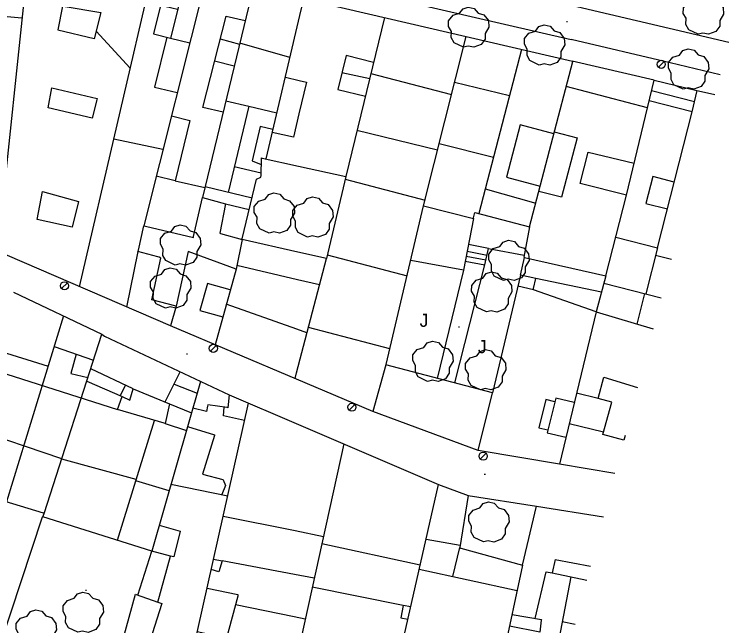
# Model space of a CAD drawing. Extents: x 431390 to 432653, y 4586754 to 4589600.
# Drawn here: x 432092.3 to 432163.1, y 4587535.4 to 4587596 of the extents above; entities that cross this region are included whole.
import ezdxf

# ---------------------------------------------------------------- set-up
doc = ezdxf.new("R2010")
doc.units = 0
for name, color, linetype in [('COM_03LS_LN', 7, 'Continuous'), ('COM_17LS_LN', 7, 'Continuous'), ('CON_01_LN', 7, 'Continuous'), ('CON_01FI_LN', 7, 'Continuous'), ('CON_03_LN', 7, 'Continuous'), ('CON_04_LN', 7, 'Continuous'), ('CON_16_LN', 7, 'Continuous'), ('CON_23_LN', 7, 'Continuous'), ('CON_29_LN', 7, 'Continuous'), ('ENE_06_PT', 7, 'Continuous'), ('ORO_03_PT', 7, 'Continuous'), ('TOP_15JA_TX', 7, 'Continuous'), ('VEG_03_PT', 7, 'Continuous'), ('VEG_04_LN', 7, 'Continuous'), ('VEG_06_LN', 7, 'Continuous')]:
    doc.layers.add(name, color=color, linetype=linetype)

msp = doc.modelspace()

# ---------------------------------------------------------------- linework, layer by layer
at = {"layer": 'COM_03LS_LN'}
for points in [[(432148.069, 4587596.828), (432163.121, 4587593.267)], [(432162.272, 4587590.047), (432157.309, 4587591.225), (432147.484, 4587593.556)]]:
    msp.add_lwpolyline(points, dxfattribs=at)
at = {"layer": 'COM_17LS_LN'}
msp.add_lwpolyline([(432070.895, 4587611.638), (432120.634, 4587599.769), (432147.484, 4587593.556)], dxfattribs=at)
at = {"layer": 'CON_01_LN'}
for points in [[(432106.208, 4587601.193), (432120.615, 4587597.708), (432120.995, 4587597.616), (432147.631, 4587591.384)], [(432155.734, 4587589.503), (432147.612, 4587591.388)], [(432155.734, 4587589.503), (432159.823, 4587588.532), (432161.753, 4587588.075)], [(432151.84, 4587550.473), (432146.326, 4587551.413), (432138.281, 4587552.763), (432127.829, 4587556.647), (432120.26, 4587559.847), (432107.753, 4587565.134), (432088.191, 4587573.557), (432088.214, 4587573.584)], [(432092.203, 4587568.485), (432100.973, 4587564.312), (432101.229, 4587564.125), (432113.576, 4587558.283), (432120.218, 4587555.446), (432134.346, 4587549.412), (432137.277, 4587548.31)], [(432144.072, 4587547.245), (432150.707, 4587546.175)]]:
    msp.add_lwpolyline(points, dxfattribs=at)
at = {"layer": 'CON_01FI_LN'}
for points in [[(432123.226, 4587571.811), (432120.378, 4587572.458), (432114.871, 4587573.708), (432114.883, 4587573.755), (432116.309, 4587579.681), (432116.733, 4587579.891), (432116.753, 4587580.055), (432116.784, 4587581.798), (432116.85, 4587581.779), (432120.458, 4587580.992), (432125.144, 4587579.971), (432123.226, 4587571.811)], [(432108.337, 4587567.104), (432105.927, 4587567.726), (432106.82, 4587571.868), (432106.643, 4587571.942), (432106.502, 4587571.98), (432104.519, 4587572.51), (432104.597, 4587572.648), (432105.12, 4587575.073), (432105.292, 4587575.039), (432110.047, 4587573.898), (432110.053, 4587573.998), (432110.937, 4587577.872), (432113.209, 4587577.237), (432112.659, 4587574.33), (432112.715, 4587574.294), (432114.871, 4587573.708), (432114.268, 4587570.766), (432109.511, 4587572.517), (432108.337, 4587567.104)], [(432139.69, 4587558.497), (432129.133, 4587561.255), (432129.151, 4587561.297), (432132.868, 4587577.053), (432137.815, 4587575.785), (432137.802, 4587575.858), (432137.941, 4587576.391), (432143.372, 4587574.965), (432142.798, 4587571.962), (432142.868, 4587571.912), (432150.929, 4587570.089), (432149.982, 4587566.519), (432143.77, 4587568.7), (432143.777, 4587568.856), (432144.01, 4587569.843), (432142.472, 4587570.176), (432139.69, 4587558.497)], [(432107.233, 4587555.449), (432107.131, 4587555.481), (432102.504, 4587556.851), (432102.972, 4587558.141), (432103.742, 4587557.759), (432104.075, 4587558.897), (432107.678, 4587557.41), (432107.233, 4587555.449)], [(432102.061, 4587530.339), (432104.307, 4587538.521), (432104.355, 4587538.486), (432106.5, 4587537.738), (432107.773, 4587542.281), (432105.905, 4587542.792), (432095.119, 4587546.184), (432095.24, 4587546.531), (432095.183, 4587546.547), (432086.343, 4587549.245), (432074.662, 4587552.564), (432075.907, 4587557.139), (432072.681, 4587558.016), (432071.631, 4587553.82), (432072.586, 4587552.504), (432072.558, 4587552.399), (432071.129, 4587547.627), (432071.982, 4587546.582), (432070.58, 4587542.529), (432071.484, 4587541.753), (432071.456, 4587541.694), (432070.713, 4587539.118)], [(432137.277, 4587548.31), (432136.457, 4587543.157), (432136.573, 4587543.097), (432142.682, 4587541.38), (432144.072, 4587547.245)]]:
    msp.add_lwpolyline(points, dxfattribs=at)
at = {"layer": 'CON_03_LN'}
for points in [[(432098.74, 4587569.015), (432106.208, 4587601.193)], [(432111.36, 4587599.947), (432105.12, 4587575.073)], [(432116, 4587598.824), (432110.937, 4587577.872)], [(432117.241, 4587581.694), (432120.598, 4587595.933), (432120.995, 4587597.616)], [(432129.002, 4587595.742), (432125.144, 4587579.971)], [(432132.868, 4587577.053), (432137.087, 4587593.851)], [(432142.586, 4587592.564), (432138.339, 4587576.286)], [(432143.372, 4587574.965), (432147.651, 4587591.379)], [(432150.929, 4587570.089), (432152.976, 4587578.109), (432155.734, 4587589.503)], [(432159.508, 4587586.369), (432160.003, 4587588.489)], [(432156.067, 4587572.881), (432159.508, 4587586.369)], [(432125.075, 4587579.677), (432133.006, 4587577.602)], [(432156.067, 4587572.881), (432154.899, 4587568.309)], [(432104.519, 4587572.51), (432103.417, 4587567.001)], [(432120.119, 4587559.907), (432120.265, 4587560.467), (432123.226, 4587571.811)], [(432114.268, 4587570.766), (432112.182, 4587563.262)], [(432150.739, 4587569.371), (432156.438, 4587567.916)], [(432108.337, 4587567.104), (432107.753, 4587565.134)], [(432149.982, 4587566.519), (432146.326, 4587551.413)], [(432097.152, 4587566.13), (432091.514, 4587547.667)], [(432095.24, 4587546.531), (432100.973, 4587564.312)], [(432129.133, 4587561.255), (432127.829, 4587556.647)], [(432110.746, 4587559.622), (432105.905, 4587542.792)], [(432138.281, 4587552.763), (432139.69, 4587558.497)], [(432108.976, 4587528.373), (432115.5, 4587557.461)], [(432124.954, 4587553.423), (432119.988, 4587530.872), (432118.821, 4587525.574)], [(432128.328, 4587522.871), (432134.346, 4587549.412)], [(432142.682, 4587541.38), (432138.762, 4587523.143), (432138.079, 4587520.171)], [(432145.915, 4587541.945), (432149.421, 4587541.297)]]:
    msp.add_lwpolyline(points, dxfattribs=at)
at = {"layer": 'CON_04_LN'}
for points in [[(432105.708, 4587599.038), (432093.684, 4587601.781), (432090.594, 4587572.522)], [(432110.633, 4587597.049), (432108.729, 4587597.527), (432107.771, 4587593.683), (432109.674, 4587593.226)], [(432100.198, 4587593.624), (432096.602, 4587594.458), (432096.629, 4587594.51), (432097.075, 4587596.869), (432097.129, 4587596.846), (432100.867, 4587596.215), (432100.198, 4587593.624)], [(432108.477, 4587596.514), (432106.781, 4587596.937), (432106.074, 4587594.106), (432107.771, 4587593.683)], [(432093.038, 4587595.667), (432089.762, 4587595.95)], [(432112.98, 4587586.325), (432110.98, 4587586.809), (432113.278, 4587595.849), (432115.183, 4587595.444)], [(432107.407, 4587593.774), (432106.169, 4587588.803), (432108.439, 4587588.304)], [(432127.91, 4587591.28), (432125.185, 4587591.947), (432124.364, 4587588.593), (432127.09, 4587587.925)], [(432114.084, 4587590.894), (432112.143, 4587591.386)], [(432119.156, 4587589.815), (432120.538, 4587589.489), (432121.252, 4587589.321), (432120.506, 4587586.157), (432119.961, 4587583.842), (432117.864, 4587584.336)], [(432155.072, 4587586.769), (432146.998, 4587588.874)], [(432100.482, 4587587.68), (432100.457, 4587587.567), (432099.986, 4587585.752), (432095.652, 4587586.753), (432096.014, 4587588.763), (432100.482, 4587587.68)], [(432159.741, 4587587.369), (432155.481, 4587588.456)], [(432113.258, 4587587.478), (432115.533, 4587586.929), (432113.479, 4587578.369)], [(432159.508, 4587586.369), (432155.239, 4587587.458)], [(432115.533, 4587586.929), (432118.32, 4587586.271)], [(432107.856, 4587585.98), (432109.67, 4587585.526), (432108.224, 4587579.522), (432111.175, 4587578.856)], [(432117.928, 4587584.609), (432116.659, 4587584.909), (432115.855, 4587581.508), (432116.773, 4587581.158)], [(432145.778, 4587584.196), (432142.449, 4587585.065), (432141.1, 4587579.898), (432144.424, 4587579)], [(432134.257, 4587582.584), (432126.254, 4587584.507)], [(432145.824, 4587584.371), (432148.082, 4587583.783), (432146.548, 4587577.894), (432144.289, 4587578.482)], [(432107.018, 4587582.639), (432102.137, 4587583.65)], [(432139.789, 4587581.845), (432134.411, 4587583.195)], [(432152.976, 4587578.109), (432148.404, 4587579.277), (432149.186, 4587582.373), (432153.745, 4587581.285)], [(432116.757, 4587580.289), (432114.093, 4587580.928)], [(432108.224, 4587579.522), (432106.354, 4587579.991)], [(432157.728, 4587579.391), (432155.581, 4587579.939), (432154.905, 4587577.293), (432157.052, 4587576.744)], [(432115.855, 4587577.795), (432111.191, 4587578.922)], [(432098.636, 4587577.481), (432098.001, 4587574.912), (432094.56, 4587575.678), (432095.075, 4587578.455), (432098.636, 4587577.481)], [(432138.974, 4587578.721), (432143.987, 4587577.324)], [(432113.209, 4587577.237), (432115.583, 4587576.665)], [(432151.912, 4587573.941), (432156.067, 4587572.881)], [(432123.316, 4587572.196), (432131.229, 4587570.107)], [(432155.877, 4587572.139), (432157.449, 4587571.748)], [(432122.544, 4587569.197), (432120.352, 4587569.715), (432114.344, 4587571.136)], [(432113.698, 4587568.715), (432111.426, 4587569.347), (432110.681, 4587566.668), (432112.953, 4587566.036)], [(432143.77, 4587568.7), (432142.209, 4587569.071)], [(432154.034, 4587565.312), (432154.805, 4587568.333)], [(432149.982, 4587566.519), (432155.627, 4587564.838)], [(432090.422, 4587562.748), (432095.628, 4587561.139)], [(432096.227, 4587563.102), (432100.144, 4587561.742)], [(432098.429, 4587562.337), (432097.888, 4587560.404), (432099.583, 4587560.002)], [(432089.836, 4587560.861), (432102.504, 4587556.851)], [(432104.075, 4587558.897), (432099.861, 4587560.864)], [(432107.248, 4587557.587), (432108.736, 4587560.573)], [(432152.839, 4587554.261), (432152.709, 4587553.792), (432150.654, 4587554.36), (432151.537, 4587557.555), (432150.172, 4587557.931), (432150.753, 4587560.041), (432154.091, 4587559.012)], [(432099.467, 4587559.64), (432102.972, 4587558.141)], [(432103.297, 4587559.26), (432102.761, 4587558.231)], [(432108.128, 4587559.352), (432110.409, 4587558.449)], [(432150.172, 4587557.931), (432148.029, 4587558.449)], [(432113.576, 4587558.283), (432113.437, 4587556.994), (432113.371, 4587557.042), (432111.477, 4587557.314), (432111.438, 4587557.17), (432111.351, 4587556.628), (432109.981, 4587556.961)], [(432145.877, 4587557.615), (432144.978, 4587557.833), (432144.299, 4587555.036), (432145.199, 4587554.817)], [(432147.806, 4587557.527), (432145.964, 4587557.973), (432145.132, 4587554.539), (432146.974, 4587554.092)], [(432107.678, 4587557.41), (432109.855, 4587556.523)], [(432115.115, 4587555.743), (432113.011, 4587556.214), (432113.082, 4587557.083)], [(432102.498, 4587543.863), (432106.181, 4587555.762)], [(432107.233, 4587555.449), (432109.345, 4587554.752)], [(432109.462, 4587555.157), (432112.13, 4587554.33), (432112.123, 4587554.275), (432110.933, 4587550.431), (432112.962, 4587549.897), (432113.004, 4587549.844), (432113.226, 4587549.312), (432112.851, 4587548.392)], [(432150.714, 4587554.576), (432147.292, 4587555.403)], [(432107.811, 4587549.417), (432113.439, 4587548.273)], [(432112.987, 4587546.256), (432120.119, 4587544.82), (432122.935, 4587544.253)], [(432106.64, 4587545.349), (432108.717, 4587544.766), (432108.083, 4587542.207), (432107.773, 4587542.281)], [(432122.78, 4587543.551), (432132.533, 4587541.415)], [(432136.488, 4587543.352), (432133.109, 4587543.956)], [(432135.761, 4587540.273), (432136.457, 4587543.157)], [(432112.033, 4587542.003), (432112.897, 4587541.81), (432112.558, 4587540.726), (432111.802, 4587540.975)], [(432145.915, 4587541.945), (432145.624, 4587540.641), (432149.051, 4587539.894)], [(432132.436, 4587540.99), (432142.148, 4587538.897)], [(432147.462, 4587540.24), (432145.688, 4587530.905), (432145.628, 4587530.945), (432144.357, 4587531.208), (432143.097, 4587525.608), (432143.222, 4587525.568), (432144.296, 4587525.404), (432143.773, 4587522.351), (432138.837, 4587523.493)], [(432111.388, 4587539.128), (432114.459, 4587538.468), (432114.428, 4587538.317), (432113.336, 4587534.147), (432113.286, 4587534.168), (432110.409, 4587534.764)], [(432106.5, 4587537.738), (432106.894, 4587537.605), (432105.486, 4587533.117), (432103.065, 4587533.996)], [(432114.212, 4587537.492), (432120.039, 4587536.294), (432121.132, 4587536.069)], [(432131.589, 4587537.254), (432130.839, 4587537.401), (432130.612, 4587536.175), (432131.315, 4587536.046)], [(432141.636, 4587536.513), (432144.544, 4587536), (432144.532, 4587535.931), (432144.384, 4587534.749), (432141.385, 4587535.346)], [(432147.896, 4587535.512), (432146.61, 4587535.757)]]:
    msp.add_lwpolyline(points, dxfattribs=at)
at = {"layer": 'CON_16_LN'}
for points in [[(432137.815, 4587575.785), (432136.822, 4587570.659), (432131.584, 4587571.61)], [(432142.472, 4587570.176), (432142.868, 4587571.912)], [(432150.498, 4587568.466), (432144.01, 4587569.843)], [(432137.277, 4587548.31), (432144.072, 4587547.245)], [(432104.513, 4587538.431), (432105.905, 4587542.792)]]:
    msp.add_lwpolyline(points, dxfattribs=at)
at = {"layer": 'CON_23_LN'}
for points in [[(432137.188, 4587572.547), (432139.164, 4587572.164)], [(432139.315, 4587572.809), (432137.313, 4587573.194)], [(432138.938, 4587571.194), (432139.315, 4587572.809)], [(432137.093, 4587572.058), (432139.051, 4587571.679)], [(432136.998, 4587571.569), (432138.938, 4587571.194)]]:
    msp.add_lwpolyline(points, dxfattribs=at)
at = {"layer": 'CON_29_LN'}
for points in [[(432103.776, 4587590.715), (432100.394, 4587594.382)], [(432112.708, 4587593.606), (432114.612, 4587593.082)], [(432119.614, 4587591.759), (432114.636, 4587593.179)], [(432124.772, 4587590.259), (432127.521, 4587589.688)], [(432127.642, 4587590.183), (432135.641, 4587588.092)], [(432135.945, 4587589.303), (432141.393, 4587587.991)], [(432121.303, 4587564.443), (432120.306, 4587564.796), (432113.299, 4587567.279)], [(432129.518, 4587562.853), (432121.445, 4587564.987)], [(432096.982, 4587551.935), (432088.006, 4587554.97)], [(432104.367, 4587549.9), (432096.978, 4587551.923)], [(432107.625, 4587548.772), (432104.324, 4587549.761)], [(432122.018, 4587540.089), (432120.078, 4587540.455), (432112.897, 4587541.81)], [(432143.928, 4587536.109), (432145.009, 4587540.731), (432145.624, 4587540.641)], [(432130.839, 4587537.401), (432121.823, 4587539.204)]]:
    msp.add_lwpolyline(points, dxfattribs=at)
at = {"layer": 'ENE_06_PT'}
for p, q in [((432156.716, 4587591.368), (432156.15, 4587590.802)), ((432097.539, 4587569.395), (432096.973, 4587568.829)), ((432112.3, 4587563.189), (432111.734, 4587562.623)), ((432126.039, 4587557.351), (432125.473, 4587556.785)), ((432139.057, 4587552.491), (432138.491, 4587551.925))]:
    msp.add_line(p, q, dxfattribs=at)
for centre in [(432156.433, 4587591.085), (432097.256, 4587569.112), (432112.017, 4587562.906), (432125.756, 4587557.068), (432138.774, 4587552.208)]:
    msp.add_circle(centre, 0.4, dxfattribs=at)
at = {"layer": 'ORO_03_PT'}
for p, q in [((432147.047, 4587595.35), (432147.147, 4587595.35)), ((432136.33, 4587565.046), (432136.43, 4587565.046)), ((432109.341, 4587562.376), (432109.441, 4587562.376)), ((432138.888, 4587550.419), (432138.988, 4587550.419)), ((432099.354, 4587538.903), (432099.454, 4587538.903))]:
    msp.add_line(p, q, dxfattribs=at)
at = {"layer": 'VEG_03_PT'}
for points in [[(432160.088, 4587594.079), (432159.161, 4587594.514), (432158.873, 4587595.035), (432158.896, 4587595.649), (432158.614, 4587596.141), (432158.622, 4587596.704), (432159.063, 4587597.239), (432159.716, 4587597.443), (432160.051, 4587597.894), (432160.577, 4587598.064), (432161.157, 4587597.931), (432161.557, 4587597.465), (432162.131, 4587597.295), (432162.565, 4587596.712), (432162.614, 4587596.07), (432162.231, 4587595.423), (432162.231, 4587594.873), (432161.859, 4587594.339), (432161.12, 4587594.064), (432160.555, 4587594.192), (432160.088, 4587594.079)], [(432136.812, 4587592.786), (432135.885, 4587593.221), (432135.597, 4587593.742), (432135.62, 4587594.356), (432135.338, 4587594.848), (432135.346, 4587595.411), (432135.787, 4587595.946), (432136.44, 4587596.15), (432136.775, 4587596.601), (432137.301, 4587596.771), (432137.881, 4587596.638), (432138.281, 4587596.172), (432138.855, 4587596.002), (432139.289, 4587595.419), (432139.338, 4587594.777), (432138.955, 4587594.13), (432138.955, 4587593.58), (432138.583, 4587593.046), (432137.844, 4587592.771), (432137.279, 4587592.899), (432136.812, 4587592.786)], [(432144.339, 4587591.015), (432143.412, 4587591.45), (432143.124, 4587591.971), (432143.147, 4587592.585), (432142.865, 4587593.077), (432142.873, 4587593.64), (432143.314, 4587594.175), (432143.967, 4587594.379), (432144.302, 4587594.83), (432144.828, 4587595), (432145.408, 4587594.867), (432145.808, 4587594.401), (432146.382, 4587594.231), (432146.816, 4587593.648), (432146.865, 4587593.006), (432146.482, 4587592.359), (432146.482, 4587591.809), (432146.11, 4587591.275), (432145.371, 4587591), (432144.806, 4587591.128), (432144.339, 4587591.015)], [(432158.618, 4587588.631), (432157.691, 4587589.066), (432157.403, 4587589.587), (432157.426, 4587590.201), (432157.144, 4587590.693), (432157.152, 4587591.256), (432157.593, 4587591.791), (432158.246, 4587591.995), (432158.581, 4587592.446), (432159.107, 4587592.616), (432159.687, 4587592.483), (432160.087, 4587592.017), (432160.661, 4587591.847), (432161.095, 4587591.264), (432161.144, 4587590.622), (432160.761, 4587589.975), (432160.761, 4587589.425), (432160.389, 4587588.891), (432159.65, 4587588.616), (432159.085, 4587588.744), (432158.618, 4587588.631)], [(432117.54, 4587574.338), (432116.613, 4587574.773), (432116.325, 4587575.294), (432116.348, 4587575.908), (432116.066, 4587576.4), (432116.074, 4587576.963), (432116.515, 4587577.498), (432117.168, 4587577.702), (432117.503, 4587578.153), (432118.029, 4587578.323), (432118.609, 4587578.19), (432119.009, 4587577.724), (432119.583, 4587577.554), (432120.017, 4587576.971), (432120.066, 4587576.329), (432119.683, 4587575.682), (432119.683, 4587575.132), (432119.311, 4587574.598), (432118.572, 4587574.323), (432118.007, 4587574.451), (432117.54, 4587574.338)], [(432121.362, 4587573.948), (432120.435, 4587574.383), (432120.147, 4587574.904), (432120.17, 4587575.518), (432119.888, 4587576.01), (432119.896, 4587576.573), (432120.337, 4587577.108), (432120.99, 4587577.312), (432121.325, 4587577.763), (432121.851, 4587577.933), (432122.431, 4587577.8), (432122.831, 4587577.334), (432123.405, 4587577.164), (432123.839, 4587576.581), (432123.888, 4587575.939), (432123.505, 4587575.292), (432123.505, 4587574.742), (432123.133, 4587574.208), (432122.394, 4587573.933), (432121.829, 4587574.061), (432121.362, 4587573.948)], [(432108.235, 4587571.173), (432107.308, 4587571.608), (432107.02, 4587572.129), (432107.043, 4587572.743), (432106.761, 4587573.235), (432106.769, 4587573.798), (432107.21, 4587574.333), (432107.863, 4587574.537), (432108.198, 4587574.988), (432108.724, 4587575.158), (432109.304, 4587575.025), (432109.704, 4587574.559), (432110.278, 4587574.389), (432110.712, 4587573.806), (432110.761, 4587573.164), (432110.378, 4587572.517), (432110.378, 4587571.967), (432110.006, 4587571.433), (432109.267, 4587571.158), (432108.702, 4587571.286), (432108.235, 4587571.173)], [(432140.799, 4587569.64), (432139.872, 4587570.075), (432139.584, 4587570.596), (432139.607, 4587571.21), (432139.325, 4587571.702), (432139.333, 4587572.265), (432139.774, 4587572.8), (432140.427, 4587573.004), (432140.762, 4587573.455), (432141.288, 4587573.625), (432141.868, 4587573.492), (432142.268, 4587573.026), (432142.842, 4587572.856), (432143.276, 4587572.273), (432143.325, 4587571.631), (432142.942, 4587570.984), (432142.942, 4587570.434), (432142.57, 4587569.9), (432141.831, 4587569.625), (432141.266, 4587569.753), (432140.799, 4587569.64)], [(432107.259, 4587566.898), (432106.332, 4587567.333), (432106.044, 4587567.854), (432106.067, 4587568.468), (432105.785, 4587568.96), (432105.793, 4587569.523), (432106.234, 4587570.058), (432106.887, 4587570.262), (432107.222, 4587570.713), (432107.748, 4587570.883), (432108.328, 4587570.75), (432108.728, 4587570.284), (432109.302, 4587570.114), (432109.736, 4587569.531), (432109.785, 4587568.889), (432109.402, 4587568.242), (432109.402, 4587567.692), (432109.03, 4587567.158), (432108.291, 4587566.883), (432107.726, 4587567.011), (432107.259, 4587566.898)], [(432139.103, 4587566.518), (432138.176, 4587566.953), (432137.888, 4587567.474), (432137.911, 4587568.088), (432137.629, 4587568.58), (432137.637, 4587569.143), (432138.078, 4587569.678), (432138.731, 4587569.882), (432139.066, 4587570.333), (432139.592, 4587570.503), (432140.172, 4587570.37), (432140.572, 4587569.904), (432141.146, 4587569.734), (432141.58, 4587569.151), (432141.629, 4587568.509), (432141.246, 4587567.862), (432141.246, 4587567.312), (432140.874, 4587566.778), (432140.135, 4587566.503), (432139.57, 4587566.631), (432139.103, 4587566.518)], [(432133.266, 4587559.633), (432132.339, 4587560.068), (432132.051, 4587560.589), (432132.074, 4587561.203), (432131.792, 4587561.695), (432131.8, 4587562.258), (432132.241, 4587562.793), (432132.894, 4587562.997), (432133.229, 4587563.448), (432133.755, 4587563.618), (432134.335, 4587563.485), (432134.735, 4587563.019), (432135.309, 4587562.849), (432135.743, 4587562.266), (432135.792, 4587561.624), (432135.409, 4587560.977), (432135.409, 4587560.427), (432135.037, 4587559.893), (432134.298, 4587559.618), (432133.733, 4587559.746), (432133.266, 4587559.633)], [(432138.501, 4587558.793), (432137.574, 4587559.228), (432137.286, 4587559.749), (432137.309, 4587560.363), (432137.027, 4587560.855), (432137.035, 4587561.418), (432137.476, 4587561.953), (432138.129, 4587562.157), (432138.464, 4587562.608), (432138.99, 4587562.778), (432139.57, 4587562.645), (432139.97, 4587562.179), (432140.544, 4587562.009), (432140.978, 4587561.426), (432141.027, 4587560.784), (432140.644, 4587560.137), (432140.644, 4587559.587), (432140.272, 4587559.053), (432139.533, 4587558.778), (432138.968, 4587558.906), (432138.501, 4587558.793)], [(432138.809, 4587543.702), (432137.882, 4587544.137), (432137.594, 4587544.658), (432137.617, 4587545.272), (432137.335, 4587545.764), (432137.343, 4587546.327), (432137.784, 4587546.862), (432138.437, 4587547.066), (432138.772, 4587547.517), (432139.298, 4587547.687), (432139.878, 4587547.554), (432140.278, 4587547.088), (432140.852, 4587546.918), (432141.286, 4587546.335), (432141.335, 4587545.693), (432140.952, 4587545.046), (432140.952, 4587544.496), (432140.58, 4587543.962), (432139.841, 4587543.687), (432139.276, 4587543.815), (432138.809, 4587543.702)], [(432098.582, 4587534.745), (432097.655, 4587535.18), (432097.367, 4587535.701), (432097.39, 4587536.315), (432097.108, 4587536.807), (432097.116, 4587537.37), (432097.557, 4587537.905), (432098.21, 4587538.109), (432098.545, 4587538.56), (432099.071, 4587538.73), (432099.651, 4587538.597), (432100.051, 4587538.131), (432100.625, 4587537.961), (432101.059, 4587537.378), (432101.108, 4587536.736), (432100.725, 4587536.089), (432100.725, 4587535.539), (432100.353, 4587535.005), (432099.614, 4587534.73), (432099.049, 4587534.858), (432098.582, 4587534.745)], [(432093.926, 4587532.978), (432092.999, 4587533.413), (432092.711, 4587533.934), (432092.734, 4587534.548), (432092.452, 4587535.04), (432092.46, 4587535.603), (432092.901, 4587536.138), (432093.554, 4587536.342), (432093.889, 4587536.793), (432094.415, 4587536.963), (432094.995, 4587536.83), (432095.395, 4587536.364), (432095.969, 4587536.194), (432096.403, 4587535.611), (432096.452, 4587534.969), (432096.069, 4587534.322), (432096.069, 4587533.772), (432095.697, 4587533.238), (432094.958, 4587532.963), (432094.393, 4587533.091), (432093.926, 4587532.978)]]:
    msp.add_lwpolyline(points, dxfattribs=at)
at = {"layer": 'VEG_04_LN'}
msp.add_lwpolyline([(432090.878, 4587533.471), (432095.072, 4587546.199)], dxfattribs=at)
at = {"layer": 'VEG_06_LN'}
for points in [[(432139.315, 4587572.809), (432142.836, 4587572.163)], [(432135.95, 4587559.474), (432138.938, 4587571.194)], [(432136.822, 4587570.659), (432134.224, 4587559.925)]]:
    msp.add_lwpolyline(points, dxfattribs=at)

# ---------------------------------------------------------------- texts
at = {"layer": 'TOP_15JA_TX'}
for p in [(432132.47, 4587565.038), (432138.249, 4587562.427)]:
    msp.add_text('J', height=1.3, dxfattribs=at).set_placement(p)

doc.saveas('drawing.dxf')
